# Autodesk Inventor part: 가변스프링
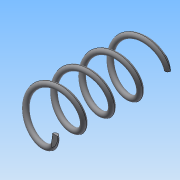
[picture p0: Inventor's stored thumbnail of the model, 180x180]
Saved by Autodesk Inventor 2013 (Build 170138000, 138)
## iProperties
Created: 2015-09
Part Number: 가변스프링
Material: 일반
Document SubType Name: Modeling
Designer: Administrator
Density: 1 g/cm^3
Mass: 0.625251 g
Surface Area: 12.7437 cm^2
Volume: 0.625251 cm^3
Author: Administrator
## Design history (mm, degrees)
sketch "스케치1"
  geometry: L1 (0, 0)-(0, 42); L2 (0, 0)-(8, 0); L3 (0, 42)-(8, 42); C1 r 1 at (8, 0)
  constraints: 6 end point, 1 centre point, 1 horizontal alignment, 1 parallel, 1 perpendicular, 1 vertical
  dimensions: "d0" = 42 distance of L1.start L1.end (derived); "d1" = 2 diameter of C1; "d2" = 16 diameter of L2.end L1
feature "코일1" sketch "스케치1" pitch "d3" = 10; turns "d5" = 4; dims "d4" = 42 (= d0), "d6" = 0, angle "d7" = 90 deg, angle "d8" = 90 deg, "d9" = 0, "d10" = 0
sketch "스케치2"
  geometry: L1 (42, 10)-(0, 10); L2 (0, 10)-(0, -10); L3 (0, -10)-(42, -10); L4 (42, -10)-(42, 10); 2 further points
  constraints: 8 end point, 2 parallel, 1 coincident, 1 horizontal, 1 midpoint, 1 perpendicular
  dimensions: "d11" = 20 distance between parallel lines of L3 L1; "d13" = 42 distance of L1.start L1.end (derived)
extrude "돌출1" sketch "스케치2" stored distance "d14" = 20; taper "d15" = 0 deg
node "솔리드1"
